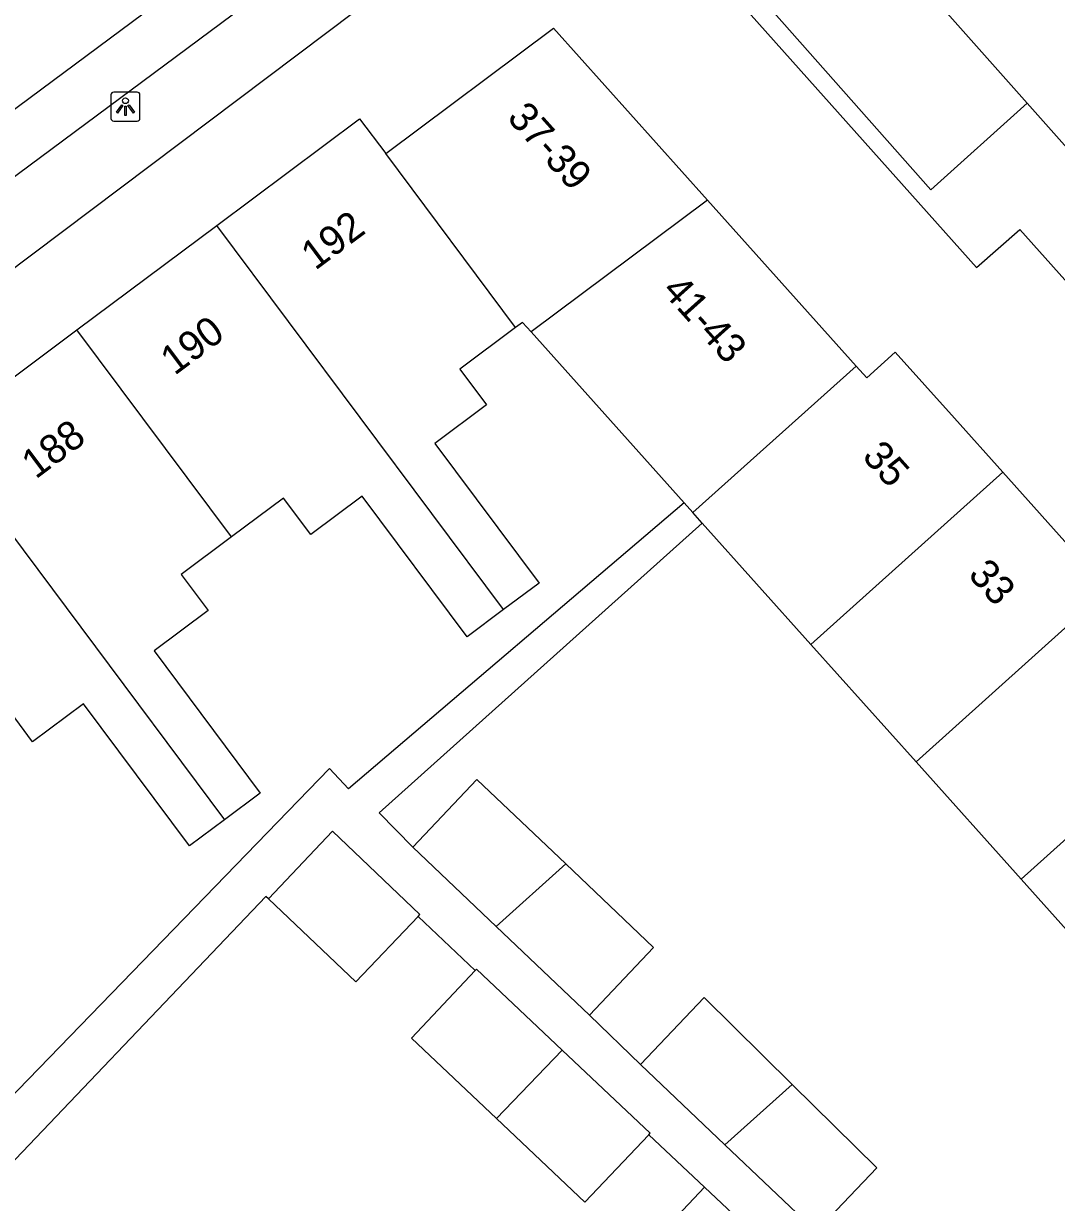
# Model space of a CAD drawing. Extents: x 158474 to 159560, y 388525 to 389605.
# Drawn here: x 159081.99 to 159117.5, y 388833.95 to 388874.47 of the extents above; entities that cross this region are included whole.
import ezdxf

# ---------------------------------------------------------------- set-up
doc = ezdxf.new("R2010")
doc.units = 0
for name, color, linetype in [('IMGEO_Lichtpunt', 7, 'Continuous'), ('IMGEO_Pand', 7, 'Continuous'), ('IMGEO_Pand_nummerreeks', 7, 'Continuous'), ('IMGEO_Rijbaan_lokaal_open', 7, 'Continuous'), ('IMGEO_Voetpad_open', 7, 'Continuous')]:
    doc.layers.add(name, color=color, linetype=linetype)

msp = doc.modelspace()

# ---------------------------------------------------------------- linework, layer by layer
at = {"layer": 'IMGEO_Lichtpunt'}
for p, q in [((159084.99, 388872.023), (159084.99, 388871.216)), ((159084.99, 388872.023), (159084.99, 388871.216)), ((159085.892, 388872.118), (159085.084, 388872.118)), ((159085.892, 388872.118), (159085.084, 388872.118)), ((159085.986, 388871.216), (159085.986, 388872.023)), ((159085.986, 388871.216), (159085.986, 388872.023)), ((159085.084, 388871.122), (159085.892, 388871.122)), ((159085.084, 388871.122), (159085.892, 388871.122))]:
    msp.add_line(p, q, dxfattribs=at)
for points in [[(159085.364, 388871.687), (159085.403, 388871.659), (159085.215, 388871.397), (159085.177, 388871.424), (159085.364, 388871.687)], [(159085.466, 388871.639), (159085.513, 388871.639), (159085.513, 388871.317), (159085.466, 388871.317), (159085.466, 388871.639)], [(159085.576, 388871.659), (159085.614, 388871.686), (159085.801, 388871.424), (159085.762, 388871.396), (159085.576, 388871.659)]]:
    msp.add_lwpolyline(points, dxfattribs=at)
msp.add_circle((159085.489, 388871.821), 0.0994, dxfattribs=at)
for centre, start, end in [((159085.084, 388872.023), 90, 180), ((159085.084, 388872.023), 90, 180), ((159085.892, 388872.023), 0, 90), ((159085.892, 388872.023), 0, 90), ((159085.084, 388871.216), 180, 270), ((159085.084, 388871.216), 180, 270), ((159085.892, 388871.216), 270, 0), ((159085.892, 388871.216), 270, 360)]:
    msp.add_arc(centre, 0.0946, start, end, dxfattribs=at)
at = {"layer": 'IMGEO_Pand'}
for points in [[(159094.436, 388870.004), (159100.206, 388874.312), (159105.501, 388868.403)], [(159088.631, 388867.539), (159093.54, 388871.203), (159094.436, 388870.004)], [(159098.9, 388864.024), (159094.436, 388870.004)], [(159105.501, 388868.403), (159099.433, 388863.873)], [(159110.609, 388862.703), (159105.501, 388868.403)], [(159083.817, 388863.945), (159088.631, 388867.539)], [(159098.49, 388854.332), (159088.631, 388867.539)], [(159098.9, 388864.024), (159096.986, 388862.595), (159097.901, 388861.369), (159096.126, 388860.044), (159099.71, 388855.242), (159098.49, 388854.332)], [(159099.433, 388863.873), (159099.139, 388864.202), (159098.9, 388864.024)], [(159079.004, 388860.352), (159083.817, 388863.945)], [(159089.13, 388856.828), (159083.817, 388863.945)], [(159099.433, 388863.873), (159104.695, 388858.002)], [(159115.654, 388859.053), (159113.994, 388860.906), (159111.959, 388863.177), (159110.975, 388862.294), (159110.609, 388862.703)], [(159104.993, 388857.67), (159110.609, 388862.703)], [(159079.004, 388860.352), (159088.891, 388847.106)], [(159109.054, 388853.137), (159115.654, 388859.053)], [(159115.654, 388859.053), (159117.398, 388857.107), (159119.27, 388855.019)], [(159098.49, 388854.332), (159097.234, 388853.394), (159093.623, 388858.23), (159091.857, 388856.912), (159090.921, 388858.165), (159089.13, 388856.828)], [(159104.993, 388857.67), (159104.695, 388858.002)], [(159105.322, 388857.302), (159104.993, 388857.67)], [(159105.322, 388857.302), (159109.054, 388853.137)], [(159089.13, 388856.828), (159087.405, 388855.54), (159088.329, 388854.303), (159086.471, 388852.916), (159090.122, 388848.025), (159088.891, 388847.106)], [(159119.27, 388855.019), (159112.67, 388849.103)], [(159112.67, 388849.103), (159109.054, 388853.137)], [(159088.891, 388847.106), (159087.689, 388846.209), (159084.042, 388851.094), (159082.294, 388849.789), (159081.394, 388850.995), (159079.531, 388849.604)], [(159116.284, 388845.07), (159122.884, 388850.986)], [(159116.284, 388845.07), (159112.67, 388849.103)], [(159095.369, 388846.169), (159097.575, 388848.491), (159100.631, 388845.587)], [(159095.549, 388843.782), (159095.614, 388843.85), (159092.606, 388846.71), (159090.402, 388844.391)], [(159098.238, 388843.442), (159095.369, 388846.169)], [(159100.631, 388845.587), (159098.238, 388843.442)], [(159100.631, 388845.587), (159103.65, 388842.718), (159101.443, 388840.396)], [(159119.899, 388841.036), (159116.284, 388845.07)], [(159090.402, 388844.391), (159093.409, 388841.532), (159095.549, 388843.782)], [(159101.443, 388840.396), (159098.238, 388843.442)], [(159098.241, 388836.836), (159095.321, 388839.596), (159097.518, 388841.921)], [(159100.499, 388839.191), (159097.562, 388841.967), (159097.518, 388841.921)], [(159108.411, 388838.012), (159105.389, 388840.994), (159103.201, 388838.691)], [(159100.499, 388839.191), (159098.241, 388836.836)], [(159103.483, 388836.282), (159103.527, 388836.329), (159100.499, 388839.191)], [(159103.201, 388838.691), (159106.097, 388835.939)], [(159106.097, 388835.939), (159108.411, 388838.012)], [(159109.241, 388832.951), (159111.322, 388835.141), (159108.411, 388838.012)], [(159098.241, 388836.836), (159101.286, 388833.958), (159103.483, 388836.282)], [(159106.097, 388835.939), (159109.241, 388832.951)], [(159106.088, 388829.354), (159103.169, 388832.113), (159105.403, 388834.476)], [(159108.339, 388831.701), (159105.403, 388834.476)]]:
    msp.add_lwpolyline(points, dxfattribs=at)
at = {"layer": 'IMGEO_Rijbaan_lokaal_open'}
for points in [[(159116.489, 388871.743), (159105.588, 388884.01)], [(159059.794, 388855.292), (159072.405, 388864.659), (159088.845, 388876.87), (159096.865, 388882.864), (159097.916, 388883.688)], [(159147.838, 388836.491), (159129.752, 388856.818), (159116.489, 388871.743)]]:
    msp.add_lwpolyline(points, dxfattribs=at)
at = {"layer": 'IMGEO_Voetpad_open'}
for points in [[(159116.489, 388871.743), (159113.174, 388868.76), (159102.05, 388881.339)], [(159057.955, 388848.239), (159075.248, 388861.255), (159101.461, 388880.986), (159114.746, 388866.089), (159116.239, 388867.395), (159118.458, 388864.905), (159121.85, 388861.096), (159125.655, 388856.825), (159129.047, 388853.017), (159132.779, 388848.828), (159136.171, 388845.02), (159145.569, 388834.47)], [(159096.885, 388880.547), (159089.961, 388875.372), (159073.604, 388863.223), (159063.098, 388855.419)], [(159104.695, 388858.002), (159093.153, 388848.171), (159092.503, 388848.873), (159077.507, 388833.404)], [(159095.369, 388846.169), (159094.214, 388847.35), (159105.322, 388857.302)], [(159090.402, 388844.391), (159090.316, 388844.473), (159079.843, 388833.493)], [(159097.518, 388841.921), (159095.549, 388843.782)], [(159103.201, 388838.691), (159101.443, 388840.396)], [(159105.403, 388834.476), (159103.483, 388836.282)]]:
    msp.add_lwpolyline(points, dxfattribs=at)

# ---------------------------------------------------------------- texts
at = {"layer": 'IMGEO_Pand_nummerreeks'}
for s, rotation, p in [('37-39', 311.8632, (159098.576, 388871.216)), ('192', 36.7371, (159092.014, 388865.971)), ('41-43', 311.8658, (159103.901, 388865.273)), ('190', 36.7422, (159087.178, 388862.36)), ('188', 36.7422, (159082.403, 388858.796)), ('35', 311.8658, (159110.785, 388859.572)), ('33', 311.864, (159114.428, 388855.508))]:
    msp.add_text(s, height=1, rotation=rotation, dxfattribs=at).set_placement(p)

doc.saveas('drawing.dxf')
